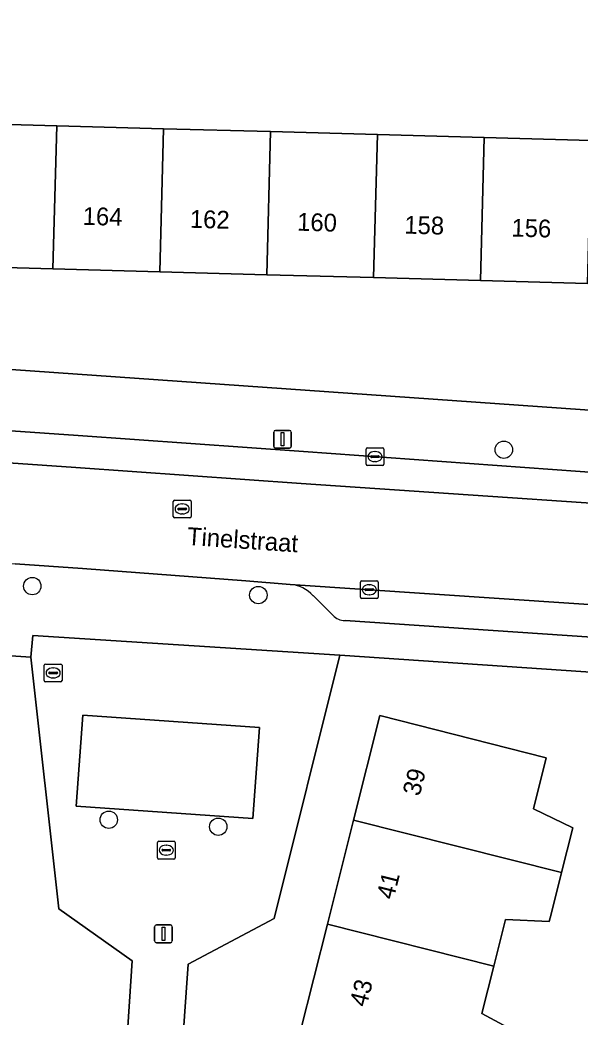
# Model space of a CAD drawing. Extents: x 159053 to 160042, y 380449 to 381423.
# Drawn here: x 159356.2 to 159387.7, y 381158.5 to 381214.5 of the extents above; entities that cross this region are included whole.
import ezdxf

# ---------------------------------------------------------------- set-up
doc = ezdxf.new("R2010")
doc.units = 0
for name, color, linetype in [('IMGEO_Boom', 7, 'Continuous'), ('IMGEO_Brandkraan', 7, 'Continuous'), ('IMGEO_Erf', 7, 'Continuous'), ('IMGEO_Kolk', 7, 'Continuous'), ('IMGEO_Lichtmast', 7, 'Continuous'), ('IMGEO_Openbare_ruimte_label', 7, 'Continuous'), ('IMGEO_Pand', 7, 'Continuous'), ('IMGEO_Pand_nummerreeks', 7, 'Continuous'), ('IMGEO_Parkeervlak_open', 7, 'Continuous'), ('IMGEO_Rijbaan_lokaal_open', 7, 'Continuous'), ('IMGEO_Rioolput', 7, 'Continuous'), ('IMGEO_Voetpad_open', 7, 'Continuous')]:
    doc.layers.add(name, color=color, linetype=linetype)

msp = doc.modelspace()

# ---------------------------------------------------------------- linework, layer by layer
at = {"layer": 'IMGEO_Boom'}
for centre in [(159383.379, 381190.391), (159356.878, 381182.728), (159369.582, 381182.225), (159361.178, 381169.6), (159367.328, 381169.21)]:
    msp.add_circle(centre, 0.489, dxfattribs=at)
at = {"layer": 'IMGEO_Brandkraan'}
for p, q in [((159357.549, 381177.426), (159357.549, 381178.278)), ((159357.624, 381178.352), (159358.476, 381178.352)), ((159357.808, 381177.846), (159357.808, 381177.858)), ((159358.246, 381177.809), (159357.848, 381177.809)), ((159357.851, 381177.895), (159358.249, 381177.895)), ((159358.037, 381178.132), (159358.062, 381178.132)), ((159358.292, 381177.858), (159358.292, 381177.846)), ((159358.55, 381178.278), (159358.55, 381177.426)), ((159358.476, 381177.352), (159357.624, 381177.352)), ((159358.06, 381177.572), (159358.035, 381177.572))]:
    msp.add_line(p, q, dxfattribs=at)
for points in [[(159357.549, 381177.426), (159357.549, 381178.278)], [(159357.624, 381178.352), (159358.476, 381178.352)], [(159358.55, 381178.278), (159358.55, 381177.426)], [(159358.476, 381177.352), (159357.624, 381177.352)]]:
    msp.add_lwpolyline(points, dxfattribs=at)
for centre, radius, start, end in [((159357.626, 381178.276), 0.0765, 91.552, 178.448), ((159357.626, 381178.276), 0.0765, 91.552, 178.448), ((159357.848, 381177.855), 0.0403, 85.8775, 175.7526), ((159357.845, 381177.845), 0.0366, 178.938, 274.7102), ((159358.249, 381177.852), 0.043, 264.8664, 352.4533), ((159358.253, 381177.857), 0.0386, 1.7309, 96.639), ((159358.474, 381178.276), 0.0765, 1.552, 88.448), ((159358.474, 381178.276), 0.0765, 1.552, 88.448), ((159357.626, 381177.428), 0.0765, 181.552, 268.448), ((159357.626, 381177.428), 0.0765, 181.552, 268.448), ((159358.474, 381177.428), 0.0765, 271.552, 358.448), ((159358.474, 381177.428), 0.0765, 271.552, 358.448)]:
    msp.add_arc(centre, radius, start, end, dxfattribs=at)
for centre, major_axis, ratio, start_param, end_param in [((159358.036, 381177.852), (-0.387, 0.002), 0.722429, 4.712389, 7.853982), ((159358.061, 381177.852), (-0.39, 0.002), 0.717154, 1.570796, 4.712389)]:
    msp.add_ellipse(centre, major_axis=major_axis, ratio=ratio, start_param=start_param, end_param=end_param, dxfattribs=at)
at = {"layer": 'IMGEO_Erf'}
for points in [[(159352.243, 381208.754), (159358.251, 381208.591), (159364.259, 381208.427), (159370.267, 381208.263), (159376.275, 381208.099), (159382.281, 381207.936), (159388.289, 381207.772), (159388.359, 381210.379), (159394.368, 381210.218), (159394.298, 381207.608), (159400.305, 381207.444), (159406.313, 381207.28), (159412.342, 381207.116), (159412.643, 381214.977)], [(159337.817, 381196.156), (159412.725, 381190.897), (159413.137, 381190.868), (159413.749, 381198.987), (159412.123, 381199.079), (159406.098, 381199.243), (159400.09, 381199.407), (159394.083, 381199.571), (159388.074, 381199.735), (159382.067, 381199.899), (159376.06, 381200.063), (159370.052, 381200.227), (159364.044, 381200.391), (159358.036, 381200.555), (159352.028, 381200.719)]]:
    msp.add_lwpolyline(points, dxfattribs=at)
for points in [[(159346.589, 381157.879), (159362.169, 381156.817), (159362.5, 381161.678), (159358.373, 381164.605), (159356.805, 381178.73), (159339.483, 381179.88), (159339.406, 381178.814), (159339.359, 381178.144), (159335.834, 381178.383), (159335.583, 381174.79), (159333.01, 381174.98), (159332.642, 381169.445), (159333.174, 381165.836), (159335.728, 381166.375), (159336.424, 381163.077), (159337.07, 381160.015), (159334.516, 381159.476), (159334.797, 381158.146), (159341.242, 381157.891), (159341.14, 381156.354), (159343.902, 381156.186), (159346.463, 381156.031)], [(159395.856, 381164.312), (159396.06, 381167.421), (159398.657, 381167.233), (159399.325, 381177.147), (159374.158, 381178.842), (159370.465, 381164.045), (159365.639, 381161.495), (159363.677, 381133.592), (159398.457, 381131.162), (159398.959, 381143.89), (159397.15, 381152.623), (159396.964, 381150.031), (159393.385, 381150.287), (159393.57, 381152.879), (159388.745, 381153.224), (159388.848, 381154.667), (159395.186, 381154.243), (159395.426, 381157.83), (159398.017, 381157.657), (159398.223, 381160.746), (159395.633, 381160.919)], [(159383.622, 381154.731), (159376.783, 381156.453), (159371.934, 381157.674), (159373.461, 381163.737), (159374.933, 381169.581), (159376.412, 381175.454), (159385.757, 381173.074), (159385.047, 381170.213), (159387.253, 381169.152), (159386.62, 381166.638), (159386.032, 381164.304), (159385.928, 381163.89), (159383.482, 381164), (159382.822, 381161.38), (159382.15, 381158.709), (159384.327, 381157.532)]]:
    msp.add_lwpolyline(points, close=True, dxfattribs=at)
at = {"layer": 'IMGEO_Kolk'}
for p, q in [((159375.634, 381189.579), (159375.634, 381190.431)), ((159375.709, 381190.505), (159376.561, 381190.505)), ((159376.122, 381190.285), (159376.147, 381190.285)), ((159376.635, 381190.431), (159376.635, 381189.579)), ((159375.893, 381189.999), (159375.893, 381190.011)), ((159376.331, 381189.962), (159375.933, 381189.962)), ((159375.936, 381190.048), (159376.334, 381190.048)), ((159376.145, 381189.725), (159376.12, 381189.725)), ((159376.377, 381190.011), (159376.377, 381189.999)), ((159376.561, 381189.505), (159375.709, 381189.505)), ((159375.316, 381182.1), (159375.316, 381182.952)), ((159375.391, 381183.026), (159376.243, 381183.026)), ((159376.317, 381182.952), (159376.317, 381182.1)), ((159375.575, 381182.52), (159375.575, 381182.532)), ((159376.013, 381182.483), (159375.615, 381182.483)), ((159375.618, 381182.569), (159376.016, 381182.569)), ((159375.804, 381182.806), (159375.829, 381182.806)), ((159376.059, 381182.532), (159376.059, 381182.52)), ((159376.243, 381182.026), (159375.391, 381182.026)), ((159375.827, 381182.246), (159375.802, 381182.246)), ((159363.906, 381167.466), (159363.906, 381168.318)), ((159363.981, 381168.392), (159364.833, 381168.392)), ((159364.907, 381168.318), (159364.907, 381167.466)), ((159364.165, 381167.886), (159364.165, 381167.898)), ((159364.603, 381167.849), (159364.205, 381167.849)), ((159364.208, 381167.935), (159364.606, 381167.935)), ((159364.394, 381168.172), (159364.419, 381168.172)), ((159364.649, 381167.898), (159364.649, 381167.886)), ((159364.833, 381167.392), (159363.981, 381167.392)), ((159364.417, 381167.612), (159364.392, 381167.612))]:
    msp.add_line(p, q, dxfattribs=at)
for points in [[(159375.634, 381189.579), (159375.634, 381190.431)], [(159375.709, 381190.505), (159376.561, 381190.505)], [(159376.635, 381190.431), (159376.635, 381189.579)], [(159376.561, 381189.505), (159375.709, 381189.505)], [(159375.316, 381182.1), (159375.316, 381182.952)], [(159375.391, 381183.026), (159376.243, 381183.026)], [(159376.317, 381182.952), (159376.317, 381182.1)], [(159376.243, 381182.026), (159375.391, 381182.026)], [(159363.906, 381167.466), (159363.906, 381168.318)], [(159363.981, 381168.392), (159364.833, 381168.392)], [(159364.907, 381168.318), (159364.907, 381167.466)], [(159364.833, 381167.392), (159363.981, 381167.392)]]:
    msp.add_lwpolyline(points, dxfattribs=at)
for centre, radius, start, end in [((159375.711, 381190.429), 0.0765, 91.552, 178.448), ((159375.711, 381190.429), 0.0765, 91.552, 178.448), ((159376.559, 381190.429), 0.0765, 1.552, 88.448), ((159376.559, 381190.429), 0.0765, 1.552, 88.448), ((159375.711, 381189.581), 0.0765, 181.552, 268.448), ((159375.711, 381189.581), 0.0765, 181.552, 268.448), ((159375.933, 381190.008), 0.0403, 85.8775, 175.7526), ((159375.93, 381189.998), 0.0366, 178.938, 274.7102), ((159376.334, 381190.005), 0.043, 264.8664, 352.4533), ((159376.338, 381190.01), 0.0386, 1.7309, 96.639), ((159376.559, 381189.581), 0.0765, 271.552, 358.448), ((159376.559, 381189.581), 0.0765, 271.552, 358.448), ((159375.393, 381182.95), 0.0765, 91.552, 178.448), ((159375.393, 381182.95), 0.0765, 91.552, 178.448), ((159376.241, 381182.95), 0.0765, 1.552, 88.448), ((159376.241, 381182.95), 0.0765, 1.552, 88.448), ((159375.615, 381182.529), 0.0403, 85.8775, 175.7526), ((159375.612, 381182.519), 0.0366, 178.938, 274.7102), ((159376.016, 381182.526), 0.043, 264.8664, 352.4533), ((159376.02, 381182.531), 0.0386, 1.7309, 96.639), ((159375.393, 381182.102), 0.0765, 181.552, 268.448), ((159375.393, 381182.102), 0.0765, 181.552, 268.448), ((159376.241, 381182.102), 0.0765, 271.552, 358.448), ((159376.241, 381182.102), 0.0765, 271.552, 358.448), ((159363.983, 381168.316), 0.0765, 91.552, 178.448), ((159363.983, 381168.316), 0.0765, 91.552, 178.448), ((159364.831, 381168.316), 0.0765, 1.552, 88.448), ((159364.831, 381168.316), 0.0765, 1.552, 88.448), ((159364.205, 381167.895), 0.0403, 85.8775, 175.7526), ((159364.202, 381167.885), 0.0366, 178.938, 274.7102), ((159364.606, 381167.892), 0.043, 264.8664, 352.4533), ((159364.61, 381167.897), 0.0386, 1.7309, 96.639), ((159363.983, 381167.468), 0.0765, 181.552, 268.448), ((159363.983, 381167.468), 0.0765, 181.552, 268.448), ((159364.831, 381167.468), 0.0765, 271.552, 358.448), ((159364.831, 381167.468), 0.0765, 271.552, 358.448)]:
    msp.add_arc(centre, radius, start, end, dxfattribs=at)
for centre, major_axis, ratio, start_param, end_param in [((159376.121, 381190.005), (-0.387, 0.002), 0.722429, 4.712389, 7.853982), ((159376.146, 381190.005), (-0.39, 0.002), 0.717154, 1.570796, 4.712389), ((159375.803, 381182.526), (-0.387, 0.002), 0.722429, 4.712389, 7.853982), ((159375.828, 381182.526), (-0.39, 0.002), 0.717154, 1.570796, 4.712389), ((159364.393, 381167.892), (-0.387, 0.002), 0.722429, 4.712389, 7.853982), ((159364.418, 381167.892), (-0.39, 0.002), 0.717154, 1.570796, 4.712389)]:
    msp.add_ellipse(centre, major_axis=major_axis, ratio=ratio, start_param=start_param, end_param=end_param, dxfattribs=at)
at = {"layer": 'IMGEO_Lichtmast'}
for p, q in [((159370.445, 381190.58), (159370.445, 381191.38)), ((159370.445, 381191.38), (159370.445, 381190.58)), ((159370.545, 381191.48), (159371.335, 381191.48)), ((159371.335, 381191.48), (159370.545, 381191.48)), ((159371.435, 381191.38), (159371.435, 381190.58)), ((159371.435, 381190.58), (159371.435, 381191.38)), ((159371.335, 381190.48), (159370.545, 381190.48)), ((159370.545, 381190.48), (159371.335, 381190.48)), ((159363.754, 381162.793), (159363.754, 381163.593)), ((159363.754, 381163.593), (159363.754, 381162.793)), ((159363.854, 381163.693), (159364.644, 381163.693)), ((159364.644, 381163.693), (159363.854, 381163.693)), ((159364.744, 381163.593), (159364.744, 381162.793)), ((159364.744, 381162.793), (159364.744, 381163.593)), ((159364.644, 381162.693), (159363.854, 381162.693)), ((159363.854, 381162.693), (159364.644, 381162.693))]:
    msp.add_line(p, q, dxfattribs=at)
for points in [[(159370.865, 381191.355), (159371.015, 381191.355), (159371.015, 381190.605), (159370.865, 381190.605), (159370.865, 381191.355)], [(159364.174, 381163.568), (159364.324, 381163.568), (159364.324, 381162.818), (159364.174, 381162.818), (159364.174, 381163.568)]]:
    msp.add_lwpolyline(points, dxfattribs=at)
for centre, start, end in [((159370.545, 381191.38), 90, 180), ((159370.545, 381191.38), 90, 180), ((159371.335, 381191.38), 0, 90), ((159371.335, 381191.38), 360, 90), ((159370.545, 381190.58), 180, 270), ((159370.545, 381190.58), 180, 270), ((159371.335, 381190.58), 270, 0), ((159371.335, 381190.58), 270, 0), ((159363.854, 381163.593), 90, 180), ((159363.854, 381163.593), 90, 180), ((159364.644, 381163.593), 0, 90), ((159364.644, 381163.593), 360, 90), ((159363.854, 381162.793), 180, 270), ((159363.854, 381162.793), 180, 270), ((159364.644, 381162.793), 270, 0), ((159364.644, 381162.793), 270, 0)]:
    msp.add_arc(centre, 0.1, start, end, dxfattribs=at)
at = {"layer": 'IMGEO_Pand'}
for points in [[(159352.243, 381208.754), (159352.028, 381200.719), (159358.036, 381200.555), (159358.251, 381208.591)], [(159364.044, 381200.391), (159364.259, 381208.427), (159358.251, 381208.591), (159358.036, 381200.555)], [(159370.052, 381200.227), (159370.267, 381208.263), (159364.259, 381208.427), (159364.044, 381200.391)], [(159370.052, 381200.227), (159376.06, 381200.063), (159376.275, 381208.099), (159370.267, 381208.263)], [(159382.067, 381199.899), (159382.281, 381207.936), (159376.275, 381208.099), (159376.06, 381200.063)], [(159388.289, 381207.772), (159382.281, 381207.936), (159382.067, 381199.899), (159388.074, 381199.735)], [(159386.62, 381166.638), (159387.253, 381169.152), (159385.047, 381170.213), (159385.757, 381173.074), (159376.412, 381175.454), (159374.933, 381169.581)], [(159386.62, 381166.638), (159374.933, 381169.581), (159373.461, 381163.737), (159382.822, 381161.38), (159383.482, 381164), (159385.928, 381163.89), (159386.032, 381164.304)], [(159373.461, 381163.737), (159371.934, 381157.674), (159376.783, 381156.453), (159383.622, 381154.731), (159384.327, 381157.532), (159382.15, 381158.709), (159382.822, 381161.38)]]:
    msp.add_lwpolyline(points, close=True, dxfattribs=at)
at = {"layer": 'IMGEO_Parkeervlak_open'}
for points in [[(159407.806, 381187.721), (159404.772, 381187.938), (159372.118, 381190.286), (159359.449, 381191.183), (159340.776, 381192.489), (159338.035, 381192.671), (159337.916, 381190.875), (159340.654, 381190.693), (159359.323, 381189.387), (159371.994, 381188.49), (159398.502, 381186.692), (159410.545, 381185.773)], [(159487.911, 381173.518), (159488.858, 381174.48), (159489.604, 381174.872), (159487.158, 381175.068), (159371.374, 381182.825)], [(159372.664, 381182.192), (159373.771, 381181.088)], [(159374.453, 381180.793), (159391.104, 381179.669)]]:
    msp.add_lwpolyline(points, dxfattribs=at)
msp.add_lwpolyline([(159369.266, 381169.669), (159369.64, 381174.79), (159359.717, 381175.487), (159359.337, 381170.372)], close=True, dxfattribs=at)
for centre, radius, start, end in [((159371.18, 381180.799), 2.035, 43.1908, 84.535), ((159374.444, 381181.708), 0.915, 222.6453, 270.5727)]:
    msp.add_arc(centre, radius, start, end, dxfattribs=at)
at = {"layer": 'IMGEO_Rijbaan_lokaal_open'}
for points in [[(159482.078, 381180.662), (159455.525, 381182.85), (159444.275, 381183.548), (159419.745, 381185.125), (159410.545, 381185.773), (159398.502, 381186.692), (159371.994, 381188.49), (159359.323, 381189.387), (159340.654, 381190.693), (159337.916, 381190.875), (159332.905, 381191.207), (159309.922, 381192.73), (159287.147, 381194.26), (159278.1, 381194.857), (159274.38, 381195.177), (159273.367, 381195.267), (159264.523, 381195.918), (159264.142, 381189.576), (159270.165, 381189.159), (159290.318, 381187.762), (159293.502, 381187.602), (159310.558, 381186.943)], [(159311.37, 381186.961), (159314.829, 381186.674), (159327.267, 381185.896), (159339.334, 381185.09), (159355.92, 381183.977), (159359.695, 381183.717), (159368.882, 381183.022), (159371.374, 381182.825), (159487.158, 381175.068), (159489.604, 381174.872), (159490.216, 381174.956), (159490.385, 381174.858)]]:
    msp.add_lwpolyline(points, dxfattribs=at)
at = {"layer": 'IMGEO_Rioolput'}
for p, q in [((159364.801, 381186.639), (159364.801, 381187.491)), ((159364.876, 381187.565), (159365.728, 381187.565)), ((159365.289, 381187.345), (159365.314, 381187.345)), ((159365.802, 381187.491), (159365.802, 381186.639)), ((159365.06, 381187.059), (159365.06, 381187.071)), ((159365.498, 381187.022), (159365.1, 381187.022)), ((159365.103, 381187.108), (159365.501, 381187.108)), ((159365.312, 381186.785), (159365.287, 381186.785)), ((159365.544, 381187.071), (159365.544, 381187.059)), ((159365.728, 381186.565), (159364.876, 381186.565))]:
    msp.add_line(p, q, dxfattribs=at)
for points in [[(159364.801, 381186.639), (159364.801, 381187.491)], [(159364.876, 381187.565), (159365.728, 381187.565)], [(159365.802, 381187.491), (159365.802, 381186.639)], [(159365.728, 381186.565), (159364.876, 381186.565)]]:
    msp.add_lwpolyline(points, dxfattribs=at)
for centre, radius, start, end in [((159364.878, 381187.489), 0.0765, 91.552, 178.448), ((159364.878, 381187.489), 0.0765, 91.552, 178.448), ((159365.726, 381187.489), 0.0765, 1.552, 88.448), ((159365.726, 381187.489), 0.0765, 1.552, 88.448), ((159365.1, 381187.068), 0.0403, 85.8775, 175.7526), ((159365.097, 381187.058), 0.0366, 178.938, 274.7102), ((159365.501, 381187.065), 0.043, 264.8664, 352.4533), ((159365.505, 381187.07), 0.0386, 1.7309, 96.639), ((159364.878, 381186.641), 0.0765, 181.552, 268.448), ((159364.878, 381186.641), 0.0765, 181.552, 268.448), ((159365.726, 381186.641), 0.0765, 271.552, 358.448), ((159365.726, 381186.641), 0.0765, 271.552, 358.448)]:
    msp.add_arc(centre, radius, start, end, dxfattribs=at)
for centre, major_axis, ratio, start_param, end_param in [((159365.288, 381187.065), (-0.387, 0.002), 0.722429, 4.712389, 7.853982), ((159365.313, 381187.065), (-0.39, 0.002), 0.717154, 1.570796, 4.712389)]:
    msp.add_ellipse(centre, major_axis=major_axis, ratio=ratio, start_param=start_param, end_param=end_param, dxfattribs=at)
at = {"layer": 'IMGEO_Voetpad_open'}
for points in [[(159337.817, 381196.156), (159338.035, 381192.671), (159340.776, 381192.489), (159359.449, 381191.183), (159372.118, 381190.286), (159404.772, 381187.938), (159407.806, 381187.721), (159407.816, 381187.861), (159408.6, 381187.806), (159411.863, 381187.621), (159411.95, 381188.985), (159412.565, 381188.953), (159412.703, 381190.629), (159412.725, 381190.897)], [(159374.158, 381178.842), (159356.901, 381179.946), (159356.805, 381178.73), (159358.373, 381164.605), (159362.5, 381161.678), (159362.169, 381156.817), (159362.043, 381154.974), (159361.392, 381145.42), (159360.782, 381137.437), (159360.526, 381133.81), (159363.677, 381133.592), (159365.639, 381161.495), (159370.465, 381164.045)], [(159359.337, 381170.372), (159359.717, 381175.487), (159369.64, 381174.79), (159369.266, 381169.669)]]:
    msp.add_lwpolyline(points, close=True, dxfattribs=at)
for points in [[(159371.374, 381182.825), (159368.882, 381183.022), (159359.695, 381183.717), (159355.92, 381183.977)], [(159312.209, 381183.497), (159318.756, 381183.227), (159332.046, 381182.37), (159331.815, 381178.679), (159333.248, 381178.562), (159335.834, 381178.383), (159339.359, 381178.144), (159339.406, 381178.814), (159339.483, 381179.88), (159356.805, 381178.73), (159356.901, 381179.946), (159374.158, 381178.842), (159399.325, 381177.147), (159400.883, 381177.042), (159464.393, 381172.763), (159465.838, 381172.666), (159491.067, 381170.966), (159495.274, 381170.535)], [(159373.771, 381181.088), (159372.664, 381182.192)], [(159391.104, 381179.669), (159374.453, 381180.793)]]:
    msp.add_lwpolyline(points, dxfattribs=at)
for centre, radius, start, end in [((159371.18, 381180.799), 2.035, 43.1908, 84.535), ((159374.444, 381181.708), 0.915, 222.6453, 270.5727)]:
    msp.add_arc(centre, radius, start, end, dxfattribs=at)

# ---------------------------------------------------------------- texts
at = {"layer": 'IMGEO_Openbare_ruimte_label'}
msp.add_text('Tinelstraat', height=1, rotation=356.1593, dxfattribs=at).set_placement((159365.55, 381185.044))
at = {"layer": 'IMGEO_Pand_nummerreeks'}
for s, rotation, p in [('164', 358.4381, (159359.703, 381203.029)), ('162', 358.4381, (159365.725, 381202.865)), ('160', 358.4381, (159371.754, 381202.701)), ('158', 358.4381, (159377.778, 381202.536)), ('156', 358.4381, (159383.798, 381202.372)), ('39', 75.8637, (159378.645, 381170.888)), ('41', 75.8637, (159377.179, 381165.071)), ('43', 75.8637, (159375.66, 381159.035))]:
    msp.add_text(s, height=1, rotation=rotation, dxfattribs=at).set_placement(p)

doc.saveas('drawing.dxf')
